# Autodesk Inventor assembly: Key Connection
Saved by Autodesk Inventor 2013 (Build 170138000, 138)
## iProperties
Created: 2015-03
Part Number: Key Connection
Document SubType Name: Assembly
Designer: Uglješa
ClientObjectVersion: 1
Author: Uglješa
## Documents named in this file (2)
- C:\Users\Uglješa\Desktop\Assembly1\Design Accelerator\Key Connection1.iam
- C:\Users\Uglješa\Documents\Inventor\Content Center Files\R2013\en-US\ISO 2491 - A\ISO 2491 - A  20 x 8 x 63.ipt
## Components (1 placed, 1 different names)
1. ISO 2491 A A  20 x 8 x 63:1
